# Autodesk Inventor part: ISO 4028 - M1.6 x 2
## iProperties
Shininess: 64.0
Length Units: 11269
Angle Units: 11279
Time Units: 11290
Mass Units: 11283
Length Display Precision: 3
Angle Display Precision: 2
Compacted: True
Created: 2004-08
Part Number: ISO 4028 - M1.6 x 2
Vendor: Autodesk Inc.
Document SubType Name: Modeling
Designer: John Blackburn
Material: Default
Description: Hexagon Socket Set Screw
Standard: ISO 4028
Density: 0.0
Volumn: 0.0
Area: 0.0
PropertySet Name: Model Information
Control State: 0
Master: False
Checked Out: False
EGR: 1
Author: John Blackburn
Revision Number: 8
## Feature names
1. Body [Revolution]
2. Chamfer1
3. Slot [Extrusion]
4. Chamfer2
